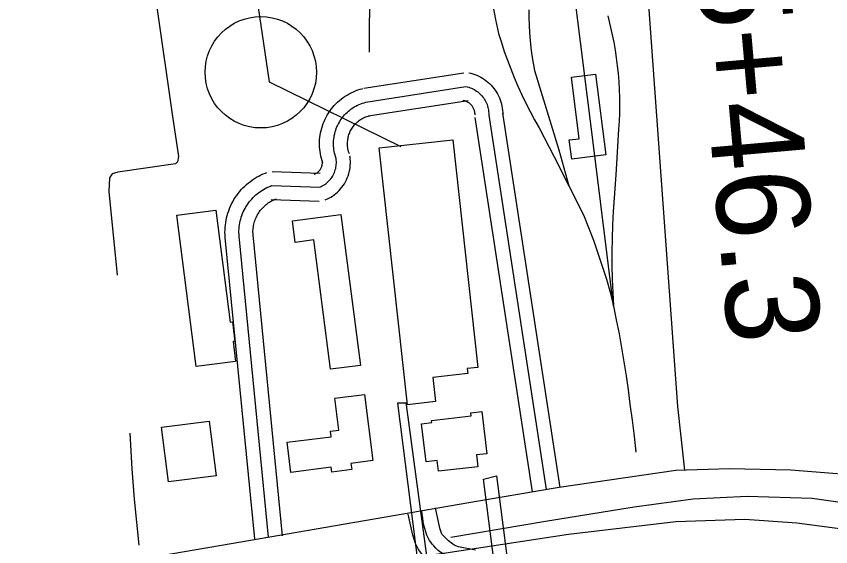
# Model space of a CAD drawing. Extents: x 3508733 to 3546731, y 546897 to 572481.
# Drawn here: x 3519217 to 3520090, y 566737 to 567306 of the extents above; entities that cross this region are included whole.
import ezdxf

# ---------------------------------------------------------------- set-up
doc = ezdxf.new("R2010")
doc.units = 0
for name, color, linetype in [('V-BLDG-OTLN', 7, 'Continuous'), ('V-DOMW-TANK', 7, 'Continuous'), ('V-LEVE-TOET', 7, 'Continuous'), ('V-RAIL-TRAK', 7, 'Continuous'), ('V-ROAD-CNTR', 7, 'Continuous'), ('V-SITE-STRC', 7, 'Continuous'), ('V-SURV-IDEN', 7, 'Continuous'), ('V-TOPO-SHOR', 7, 'Continuous'), ('V-UTIL-LINE', 7, 'Continuous')]:
    doc.layers.add(name, color=color, linetype=linetype)

msp = doc.modelspace()

# ---------------------------------------------------------------- linework, layer by layer
at = {"layer": 'V-BLDG-OTLN'}
for points in [[(3519838.33, 567243.48), (3519849.36, 567157.02), (3519812.75, 567152.35), (3519810.13, 567172.94), (3519820.72, 567174.29), (3519812.31, 567240.16)], [(3519606.23, 567164.36), (3519685.18, 567173.12), (3519712.21, 566929.25), (3519700.77, 566927.99), (3519701.36, 566922.65), (3519663.69, 566918.47), (3519666.57, 566892.49), (3519636.74, 566889.24)], [(3519389.36, 567092.33), (3519431.17, 567097.69), (3519446.57, 566977.72), (3519449, 566978.03), (3519451.69, 566957.08), (3519449.75, 566956.83), (3519452.47, 566935.69), (3519410.17, 566930.26)], [(3519565.19, 567093.07), (3519586.2, 566931.4), (3519554.3, 566927.25), (3519536.29, 567065.81), (3519516.41, 567063.22), (3519513.41, 567086.34)], [(3519511.75, 566816.75), (3519507.71, 566849.06), (3519554.79, 566854.96), (3519554.07, 566860.7), (3519562.94, 566861.82), (3519558.62, 566896.33), (3519590.7, 566900.34), (3519599.6, 566829.33), (3519576.06, 566826.38), (3519576.91, 566819.63), (3519555.63, 566816.97), (3519554.98, 566822.16)], [(3519716.52, 566881.83), (3519721.72, 566836.63), (3519710.71, 566835.36), (3519712.16, 566822.78), (3519669.91, 566817.92), (3519668.6, 566829.33), (3519656.52, 566827.95), (3519651.83, 566868.76), (3519662.72, 566870.01), (3519662.45, 566872.35), (3519704.91, 566877.23), (3519704.54, 566880.45)], [(3519424.08, 566871.56), (3519431.49, 566812.94), (3519380.42, 566806.48), (3519373.04, 566865.11)]]:
    msp.add_lwpolyline(points, close=True, dxfattribs=at)
at = {"layer": 'V-DOMW-TANK'}
msp.add_circle((3519479.46, 567245.5), 59.69, dxfattribs=at)
at = {"layer": 'V-LEVE-TOET'}
msp.add_lwpolyline([(3519136.95, 566645.72), (3519372.12, 566675.92), (3519489.29, 566696.05), (3519621.78, 566720.12), (3519657.19, 566727.44), (3519677.73, 566730.33), (3519809.4, 566750.53), (3519924.32, 566763.95), (3519998.4, 566766.58), (3520053.8, 566762.46), (3520145.94, 566750.55), (3520240.34, 566733.18), (3520349.82, 566712.15), (3520483.71, 566688.9), (3520602.97, 566675.12), (3520716.83, 566664.12), (3520853.14, 566649.76), (3521009.68, 566640.98), (3521180.11, 566626.23), (3521374.6, 566613.53), (3521554.75, 566602.16), (3521650.47, 566597.95), (3521677.61, 566597.25)], dxfattribs=at)
at = {"layer": 'V-RAIL-TRAK'}
for points in [[(3519857.35, 566994.94), (3519836.94, 567158.93), (3519814.73, 567338.13), (3519811.57, 567364.3), (3519808.17, 567390.45), (3519804.51, 567416.55), (3519800.61, 567442.62), (3519796.46, 567468.66), (3519792.07, 567494.65), (3519789.25, 567504.53), (3519786.22, 567514.34), (3519782.98, 567524.08), (3519779.52, 567533.75), (3519775.85, 567543.34), (3519771.97, 567552.85), (3519767.88, 567562.27)], [(3519728.19, 567317.2), (3519731.17, 567302.11), (3519734.38, 567287.07), (3519737.29, 567277.47), (3519740.41, 567267.93), (3519743.74, 567258.47), (3519747.28, 567249.08), (3519751.02, 567239.77), (3519754.96, 567230.55), (3519759.11, 567221.41), (3519763.46, 567212.36), (3519768, 567203.42), (3519772.73, 567194.58), (3519777.66, 567185.84), (3519793.77, 567154.92), (3519809.64, 567123.88), (3519825.25, 567092.71), (3519830.69, 567079.12), (3519835.86, 567065.43), (3519840.79, 567051.65), (3519845.46, 567037.78), (3519849.87, 567023.83), (3519854.02, 567009.8), (3519857.35, 566994.94), (3519860.48, 566980.04), (3519863.41, 566965.1), (3519866.14, 566950.12), (3519868.66, 566935.11), (3519870.98, 566920.06), (3519873.09, 566904.99), (3519875, 566889.89), (3519877.5, 566872.72), (3519879.67, 566855.51), (3519881.51, 566838.26)], [(3519766.71, 567312.49), (3519766.77, 567304.29), (3519767.03, 567296.08), (3519767.5, 567287.9), (3519768.16, 567279.72), (3519769.02, 567271.56), (3519770.09, 567263.43), (3519771.35, 567255.32), (3519772.81, 567247.25), (3519798.87, 567162.31), (3519809.64, 567123.88)], [(3519851.33, 567305.82), (3519857.69, 567277.65), (3519859.19, 567269.29), (3519860.48, 567260.89), (3519861.56, 567252.47), (3519862.44, 567244.02), (3519863.12, 567235.55), (3519863.58, 567227.08), (3519863.84, 567218.59), (3519863.9, 567210.09), (3519863.75, 567201.6), (3519863.39, 567193.12), (3519862.82, 567184.64), (3519861.55, 567160.05), (3519859.99, 567135.48), (3519858.14, 567110.93), (3519857.21, 567096.45), (3519856.51, 567081.96), (3519856.06, 567067.45), (3519855.84, 567052.95), (3519855.86, 567038.44), (3519856.12, 567023.93), (3519856.62, 567009.43), (3519857.35, 566994.94)]]:
    msp.add_lwpolyline(points, dxfattribs=at)
at = {"layer": 'V-ROAD-CNTR'}
for points in [[(3519844.72, 568199.32), (3519844.32, 568081.51), (3519894.71, 567322.5), (3519926.04, 566887.44), (3519933.41, 566818.92)], [(3519589.81, 567228.3), (3519696.91, 567245.07)], [(3519702.53, 567244.89), (3519704.42, 567244.46), (3519706.67, 567243.83), (3519708.87, 567243.09), (3519711.04, 567242.24), (3519713.16, 567241.28), (3519715.23, 567240.21), (3519717.24, 567239.03), (3519719.19, 567237.75), (3519721.06, 567236.38), (3519722.88, 567234.91), (3519724.6, 567233.35), (3519726.25, 567231.7), (3519727.81, 567229.97), (3519729.28, 567228.16), (3519730.65, 567226.28), (3519731.93, 567224.34), (3519733.1, 567222.32), (3519734.17, 567220.26), (3519735.14, 567218.13), (3519735.99, 567215.97), (3519736.73, 567213.76), (3519737.36, 567211.52), (3519737.87, 567209.24), (3519738.26, 567206.95), (3519738.53, 567204.64), (3519738.69, 567202.31), (3519738.73, 567200.09), (3519738.7, 567199.07)], [(3519545.95, 567148.44), (3519545.23, 567150.56), (3519544.51, 567153), (3519543.9, 567155.46), (3519543.39, 567157.95), (3519542.98, 567160.46), (3519542.68, 567162.99), (3519542.48, 567165.52), (3519542.39, 567168.07), (3519542.41, 567170.6), (3519542.53, 567173.15), (3519542.76, 567175.68), (3519543.09, 567178.2), (3519543.53, 567180.7), (3519544.07, 567183.19), (3519544.72, 567185.65), (3519545.47, 567188.08), (3519546.32, 567190.47), (3519547.27, 567192.84), (3519548.31, 567195.15), (3519549.45, 567197.42), (3519550.69, 567199.65), (3519552.01, 567201.82), (3519553.43, 567203.93), (3519554.93, 567205.98), (3519556.52, 567207.96), (3519558.19, 567209.88), (3519559.94, 567211.73), (3519561.76, 567213.5), (3519563.66, 567215.2), (3519565.62, 567216.81), (3519567.65, 567218.34), (3519569.74, 567219.79), (3519571.89, 567221.14), (3519574.1, 567222.41), (3519576.36, 567223.58), (3519578.66, 567224.66), (3519581, 567225.64), (3519583.39, 567226.52), (3519585.81, 567227.3), (3519588.1, 567227.93), (3519588.41, 567228.01)], [(3519592.13, 567213.48), (3519699.23, 567230.25)], [(3519699.23, 567230.25), (3519700.76, 567229.91), (3519702.26, 567229.49), (3519703.74, 567228.99), (3519705.19, 567228.42), (3519706.61, 567227.78), (3519707.99, 567227.06), (3519709.34, 567226.27), (3519710.64, 567225.42), (3519711.9, 567224.5), (3519713.11, 567223.52), (3519714.27, 567222.47), (3519715.37, 567221.37), (3519716.41, 567220.21), (3519717.4, 567219), (3519718.32, 567217.74), (3519719.17, 567216.44), (3519719.96, 567215.09), (3519720.68, 567213.71), (3519721.32, 567212.29), (3519721.89, 567210.84), (3519722.39, 567209.36), (3519722.81, 567207.86), (3519723.15, 567206.33), (3519723.41, 567204.8), (3519723.59, 567203.25), (3519723.7, 567201.69), (3519723.72, 567200.13), (3519723.71, 567199.4)], [(3519560.15, 567153.27), (3519559.53, 567155.09), (3519558.99, 567156.92), (3519558.53, 567158.78), (3519558.14, 567160.66), (3519557.84, 567162.55), (3519557.61, 567164.46), (3519557.46, 567166.37), (3519557.39, 567168.28), (3519557.41, 567170.2), (3519557.5, 567172.11), (3519557.67, 567174.02), (3519557.92, 567175.92), (3519558.25, 567177.81), (3519558.66, 567179.68), (3519559.15, 567181.53), (3519559.71, 567183.37), (3519560.35, 567185.17), (3519561.07, 567186.95), (3519561.85, 567188.7), (3519562.71, 567190.41), (3519563.65, 567192.09), (3519564.65, 567193.72), (3519565.71, 567195.31), (3519566.85, 567196.86), (3519568.04, 567198.35), (3519569.3, 567199.8), (3519570.62, 567201.19), (3519571.99, 567202.53), (3519573.42, 567203.81), (3519574.9, 567205.02), (3519576.43, 567206.18), (3519578.01, 567207.27), (3519579.63, 567208.29), (3519581.29, 567209.24), (3519582.99, 567210.12), (3519584.73, 567210.94), (3519586.5, 567211.68), (3519588.29, 567212.34), (3519590.12, 567212.93), (3519591.97, 567213.44), (3519592.13, 567213.48)], [(3519594.45, 567198.66), (3519701.55, 567215.43)], [(3519695.94, 567215.62), (3519697.09, 567215.36), (3519697.85, 567215.15), (3519698.6, 567214.9), (3519699.33, 567214.61), (3519700.05, 567214.28), (3519700.75, 567213.92), (3519701.44, 567213.52), (3519702.1, 567213.09), (3519702.73, 567212.62), (3519703.34, 567212.12), (3519703.93, 567211.59), (3519704.49, 567211.03), (3519705.02, 567210.45), (3519705.52, 567209.84), (3519705.98, 567209.2), (3519706.41, 567208.54), (3519706.81, 567207.86), (3519707.18, 567207.15), (3519707.5, 567206.44), (3519707.79, 567205.7), (3519708.04, 567204.95), (3519708.25, 567204.19), (3519708.43, 567203.42), (3519708.56, 567202.64), (3519708.65, 567201.86), (3519708.71, 567201.07), (3519708.72, 567200.18), (3519708.71, 567199.73)], [(3519574.35, 567158.1), (3519573.83, 567159.62), (3519573.47, 567160.85), (3519573.16, 567162.1), (3519572.9, 567163.37), (3519572.69, 567164.64), (3519572.54, 567165.92), (3519572.44, 567167.21), (3519572.4, 567168.5), (3519572.4, 567169.79), (3519572.47, 567171.08), (3519572.58, 567172.36), (3519572.75, 567173.64), (3519572.97, 567174.92), (3519573.25, 567176.17), (3519573.58, 567177.42), (3519573.96, 567178.66), (3519574.39, 567179.87), (3519574.87, 567181.07), (3519575.4, 567182.25), (3519575.98, 567183.4), (3519576.6, 567184.53), (3519577.28, 567185.62), (3519578, 567186.69), (3519578.76, 567187.74), (3519579.57, 567188.75), (3519580.41, 567189.72), (3519581.3, 567190.66), (3519582.22, 567191.55), (3519583.18, 567192.41), (3519584.18, 567193.24), (3519585.21, 567194.01), (3519586.27, 567194.74), (3519587.37, 567195.43), (3519588.48, 567196.07), (3519589.63, 567196.67), (3519590.8, 567197.22), (3519591.99, 567197.71), (3519593.2, 567198.16), (3519594.42, 567198.56), (3519595.83, 567198.95), (3519595.85, 567198.95)], [(3519723.71, 567199.4), (3519785.16, 566798.21)], [(3519738.53, 567201.67), (3519799.99, 566800.48)], [(3519708.88, 567197.13), (3519770.33, 566795.94)], [(3519548.6, 567108.64), (3519550.35, 567109.4), (3519552.41, 567110.44), (3519554.42, 567111.58), (3519556.36, 567112.82), (3519558.23, 567114.16), (3519560.03, 567115.61), (3519561.75, 567117.14), (3519563.39, 567118.77), (3519564.94, 567120.48), (3519566.39, 567122.26), (3519567.76, 567124.13), (3519569.02, 567126.06), (3519570.17, 567128.05), (3519571.22, 567130.11), (3519572.16, 567132.21), (3519572.99, 567134.36), (3519573.7, 567136.56), (3519574.29, 567138.79), (3519574.77, 567141.05), (3519575.13, 567143.32), (3519575.36, 567145.62), (3519575.47, 567147.92), (3519575.47, 567150.23), (3519575.34, 567152.53), (3519575.1, 567154.69), (3519574.99, 567155.42)], [(3519536.6, 567136.14), (3519537.63, 567136.59), (3519538.27, 567136.91), (3519538.89, 567137.26), (3519539.51, 567137.65), (3519540.09, 567138.07), (3519540.65, 567138.52), (3519541.19, 567139), (3519541.7, 567139.51), (3519542.18, 567140.04), (3519542.64, 567140.6), (3519543.06, 567141.18), (3519543.45, 567141.78), (3519543.82, 567142.41), (3519544.14, 567143.05), (3519544.44, 567143.71), (3519544.7, 567144.38), (3519544.92, 567145.06), (3519545.1, 567145.76), (3519545.25, 567146.46), (3519545.36, 567147.17), (3519545.44, 567147.89), (3519545.47, 567148.61), (3519545.47, 567149.33), (3519545.43, 567150.05), (3519545.34, 567150.9), (3519545.3, 567151.12)], [(3519542.6, 567122.39), (3519543.99, 567122.99), (3519545.34, 567123.67), (3519546.66, 567124.42), (3519547.93, 567125.24), (3519549.16, 567126.12), (3519550.34, 567127.06), (3519551.47, 567128.07), (3519552.54, 567129.14), (3519553.56, 567130.26), (3519554.52, 567131.43), (3519555.41, 567132.65), (3519556.24, 567133.92), (3519556.99, 567135.23), (3519557.68, 567136.58), (3519558.3, 567137.96), (3519558.84, 567139.37), (3519559.31, 567140.81), (3519559.7, 567142.27), (3519560.01, 567143.75), (3519560.24, 567145.25), (3519560.4, 567146.75), (3519560.47, 567148.27), (3519560.47, 567149.78), (3519560.38, 567151.29), (3519560.22, 567152.79), (3519560.15, 567153.27)], [(3519441.26, 567068.86), (3519441.11, 567071.21), (3519441.05, 567073.85), (3519441.09, 567076.49), (3519441.23, 567079.13), (3519441.48, 567081.76), (3519441.82, 567084.38), (3519442.27, 567086.98), (3519442.82, 567089.57), (3519443.47, 567092.13), (3519444.22, 567094.66), (3519445.06, 567097.16), (3519446, 567099.63), (3519447.04, 567102.07), (3519448.17, 567104.45), (3519449.39, 567106.79), (3519450.71, 567109.09), (3519452.11, 567111.33), (3519453.6, 567113.51), (3519455.17, 567115.64), (3519456.82, 567117.7), (3519458.55, 567119.7), (3519460.35, 567121.62), (3519462.24, 567123.48), (3519464.19, 567125.26), (3519466.2, 567126.97), (3519468.29, 567128.6), (3519470.44, 567130.14), (3519472.64, 567131.59), (3519474.89, 567132.97), (3519477.2, 567134.25), (3519479.56, 567135.44), (3519481.97, 567136.54), (3519484.36, 567137.53), (3519485.79, 567138.07)], [(3519491.54, 567139.01), (3519543.08, 567137.38)], [(3519456.23, 567069.8), (3519456.1, 567071.85), (3519456.05, 567073.91), (3519456.08, 567075.97), (3519456.2, 567078.03), (3519456.39, 567080.08), (3519456.66, 567082.12), (3519457.01, 567084.15), (3519457.43, 567086.17), (3519457.94, 567088.16), (3519458.52, 567090.14), (3519459.18, 567092.09), (3519459.91, 567094.01), (3519460.72, 567095.91), (3519461.6, 567097.77), (3519462.56, 567099.6), (3519463.58, 567101.38), (3519464.67, 567103.13), (3519465.83, 567104.83), (3519467.06, 567106.49), (3519468.34, 567108.1), (3519469.69, 567109.65), (3519471.1, 567111.16), (3519472.57, 567112.6), (3519474.09, 567113.99), (3519475.66, 567115.32), (3519477.28, 567116.59), (3519478.96, 567117.79), (3519480.67, 567118.93), (3519482.43, 567120), (3519484.23, 567121), (3519486.07, 567121.93), (3519487.94, 567122.78), (3519489.85, 567123.57), (3519491.06, 567124.02)], [(3519491.06, 567124.02), (3519542.6, 567122.39)], [(3519471.2, 567070.74), (3519471.09, 567072.5), (3519471.06, 567073.98), (3519471.08, 567075.46), (3519471.16, 567076.93), (3519471.29, 567078.4), (3519471.49, 567079.86), (3519471.74, 567081.32), (3519472.05, 567082.77), (3519472.41, 567084.2), (3519472.83, 567085.61), (3519473.3, 567087.02), (3519473.82, 567088.39), (3519474.4, 567089.75), (3519475.04, 567091.09), (3519475.72, 567092.4), (3519476.45, 567093.68), (3519477.24, 567094.93), (3519478.07, 567096.15), (3519478.94, 567097.34), (3519479.87, 567098.49), (3519480.84, 567099.61), (3519481.85, 567100.69), (3519482.9, 567101.72), (3519483.99, 567102.72), (3519485.12, 567103.67), (3519486.28, 567104.58), (3519487.48, 567105.44), (3519488.71, 567106.26), (3519489.97, 567107.03), (3519491.26, 567107.74), (3519492.58, 567108.41), (3519493.92, 567109.02), (3519495.34, 567109.61), (3519496.33, 567109.98)], [(3519490.59, 567109.03), (3519542.13, 567107.4)], [(3519472.88, 566745.63), (3519441.3, 567068.34)], [(3519487.81, 566747.09), (3519456.23, 567069.8)], [(3519502.74, 566748.56), (3519471.16, 567071.26)], [(3522650.39, 566663.25), (3522634.35, 566663.45), (3522353.7, 566667.05), (3522105.95, 566675.27), (3521836.86, 566682.37), (3521565.17, 566686.96), (3521362.69, 566692.15), (3521174.26, 566698.47), (3521015.44, 566705.68), (3520878.25, 566712.31), (3520726.49, 566727.25), (3520530.94, 566752.55), (3520369.51, 566774.01), (3520232.86, 566795.23), (3520146.65, 566811.14), (3520047.56, 566818.9), (3519981.94, 566820.36), (3519924.18, 566818.65), (3519799.14, 566800.62), (3519712.95, 566785.8)], [(3519712.95, 566785.8), (3519437.37, 566738.42), (3518962.97, 566657.35), (3518684.89, 566607.1), (3518544.78, 566581.1), (3518316.18, 566525.03), (3517942.23, 566439.4), (3517865.78, 566419.68)], [(3519662.83, 566719.14), (3519660.52, 566721.02), (3519654.01, 566727.37), (3519651.48, 566730.09), (3519647.97, 566734.77), (3519645.15, 566740.42), (3519642.46, 566749.44), (3519637.35, 566772)], [(3519709.71, 566733.42), (3519691.18, 566737.02), (3519687.29, 566738.36), (3519685.21, 566739.6), (3519680.51, 566743.43), (3519675.47, 566748.35), (3519674.52, 566749.36), (3519673.61, 566750.59), (3519673.16, 566751.49), (3519671.5, 566757.05), (3519666.61, 566778.63)]]:
    msp.add_lwpolyline(points, dxfattribs=at)
msp.add_spline([(3520032.04, 566350.14), (3520029.74, 566403.27), (3520019.95, 566487.99), (3520012.74, 566559.19), (3520011.49, 566593.15), (3520009.1, 566608.38), (3519990.43, 566631.88), (3519954.1, 566661.41), (3519924.22, 566669.51), (3519881.26, 566676.74), (3519812.86, 566698.04), (3519749.1, 566710.48), (3519687.29, 566722.5), (3519664.74, 566737.86), (3519659.15, 566745.95), (3519651.98, 566775.32)], degree=3, dxfattribs=at)
at = {"layer": 'V-SITE-STRC'}
for p, q in [((3519626, 566890.71), (3519667.16, 566567.96)), ((3519678.3, 566569.46), (3519635.69, 566889.05)), ((3519718.27, 566809.26), (3519731.91, 566812.99))]:
    msp.add_line(p, q, dxfattribs=at)
for points in [[(3519635.69, 566889.05), (3519635.32, 566890.99), (3519626, 566890.71)], [(3519731.91, 566812.99), (3519783.99, 566410.81), (3519826.95, 566127.19), (3519804.79, 566125.51), (3519769.63, 566411.36), (3519733.6, 566689.46), (3519718.27, 566809.26)]]:
    msp.add_lwpolyline(points, dxfattribs=at)
at = {"layer": 'V-TOPO-SHOR'}
for points in [[(3519331.58, 567585.16), (3519355.16, 567408.38), (3519367.88, 567315.24), (3519384.29, 567200.59), (3519391.06, 567155.4), (3519390.21, 567149.5), (3519388.02, 567147.36), (3519326.05, 567138.42), (3519320.12, 567136.51), (3519317.12, 567132.41), (3519316.56, 567117.84), (3519325.37, 567027.9)], [(3519598.59, 567578.11), (3519597.79, 567533.21), (3519596.81, 567460.4), (3519595.72, 567389.72), (3519595.86, 567340.7), (3519595.44, 567267.18)], [(3519339.17, 566858.63), (3519341.29, 566820.58), (3519343.87, 566787.85), (3519348.63, 566738.55)], [(3519683.12, 566747.34), (3519784.65, 566764.41), (3519879.57, 566779.82), (3519942.73, 566788.26), (3520000.86, 566791.16), (3520070.44, 566789.17), (3520150.42, 566777.74), (3520269.59, 566760.31)]]:
    msp.add_lwpolyline(points, dxfattribs=at)
at = {"layer": 'V-UTIL-LINE'}
msp.add_lwpolyline([(3519440.39, 567604.34), (3519456.42, 567478.32), (3519470.56, 567356.21), (3519488.59, 567235.22), (3519629.55, 567166.03)], dxfattribs=at)

# ---------------------------------------------------------------- texts
at = {"layer": 'V-SURV-IDEN'}
msp.add_text('4595+46.3', height=100, rotation=275.06583, dxfattribs=at).set_placement((3519925.04, 567585.47))

doc.saveas('drawing.dxf')
